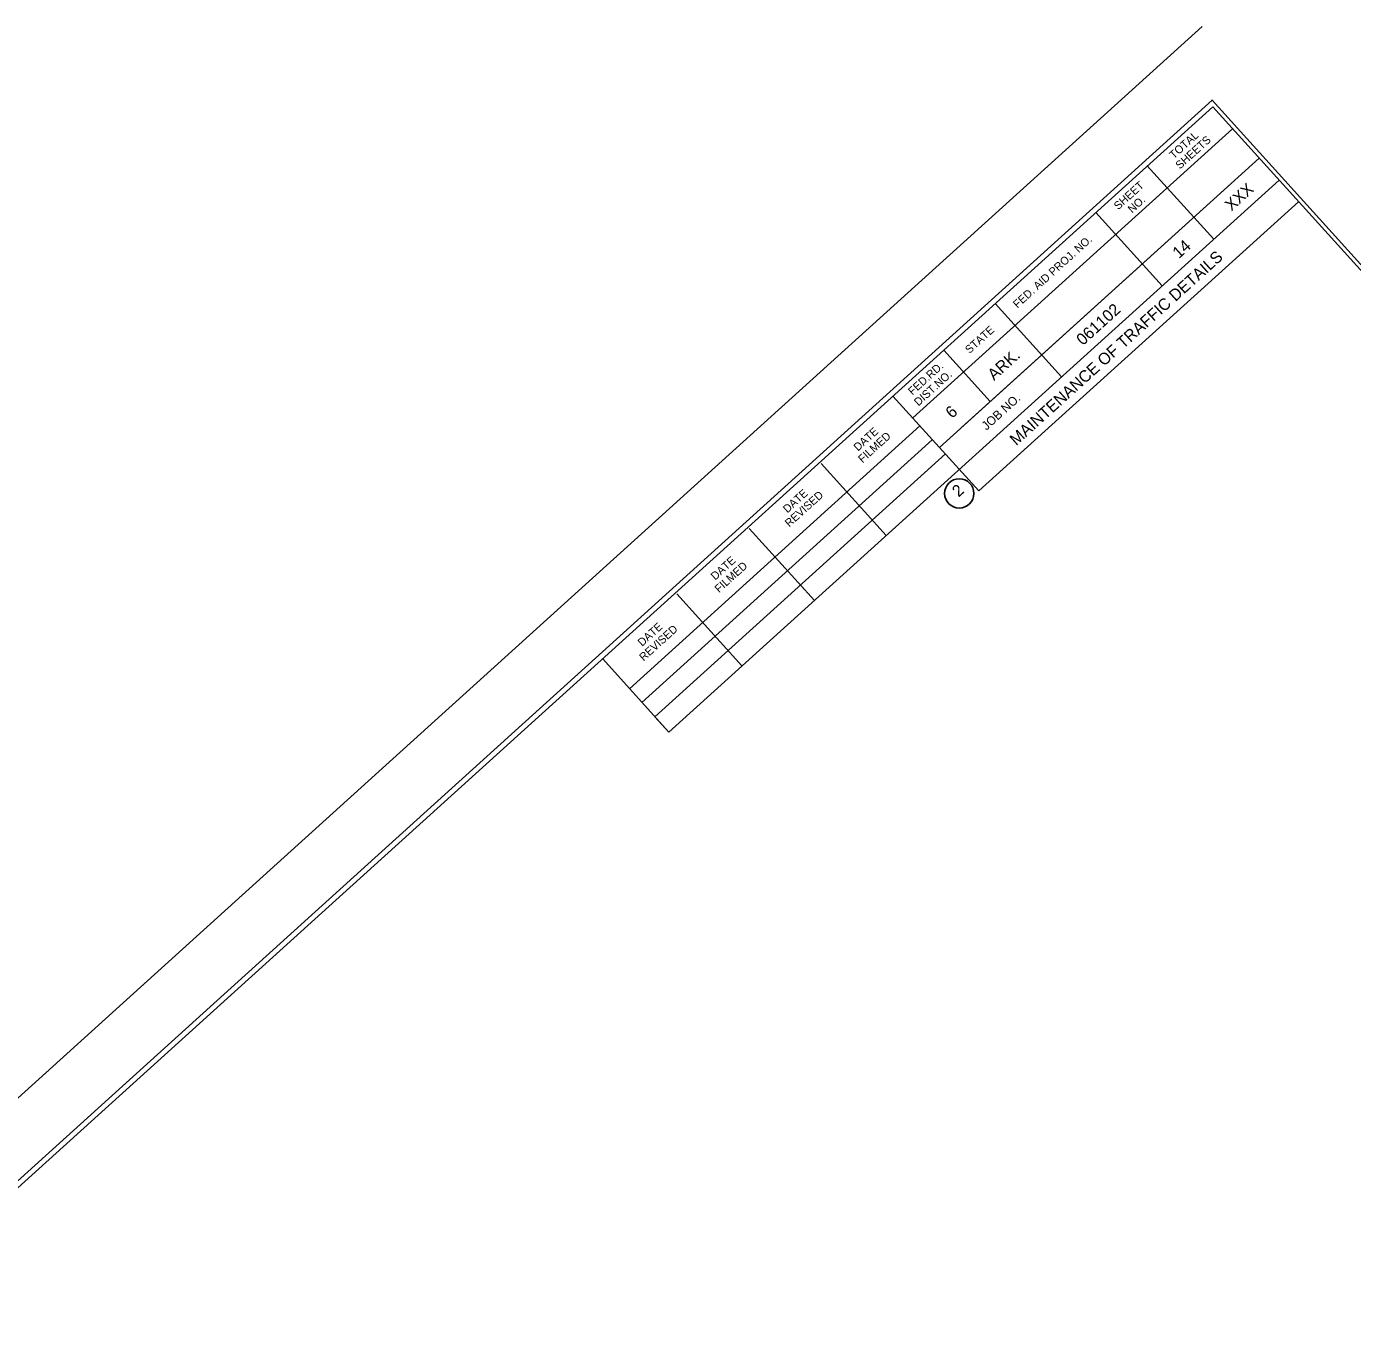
# Model space of a CAD drawing. Extents: x 1307930 to 1312775, y 238372 to 242903.
# Drawn here: x 1311449 to 1312112, y 242257 to 242903 of the extents above; entities that cross this region are included whole.
import ezdxf

# ---------------------------------------------------------------- set-up
doc = ezdxf.new("R2010")
doc.units = 0
doc.layers.add('R_Base', color=7, linetype='Continuous')

msp = doc.modelspace()

# ---------------------------------------------------------------- linework, layer by layer
at = {"layer": 'R_Base'}
for p, q in [((1312036.92, 242903.07), (1310731.77, 241722.32)), ((1310869.87, 241802.41), (1312042.27, 242862.95)), ((1312731.45, 242101.12), (1312042.27, 242862.95)), ((1312052.16, 242851.94), (1311892.32, 242707.47)), ((1312052.07, 242852.12), (1312052.07, 242852.12)), ((1312065.55, 242837.21), (1311905.67, 242692.65)), ((1311916.64, 242702.57), (1312065.55, 242837.21)), ((1312009.54, 242833.47), (1312042.75, 242796.76)), ((1312075.41, 242826.31), (1311770.33, 242550.39)), ((1311925.33, 242670.92), (1312085.17, 242815.52)), ((1311983.8, 242810.12), (1312016.91, 242773.52)), ((1311933.52, 242764.56), (1311966.63, 242727.97)), ((1311907.82, 242741.32), (1311931.03, 242715.59)), ((1311882.32, 242718.31), (1311925.33, 242670.92)), ((1311750.64, 242572.08), (1311895.82, 242703.43)), ((1311756.91, 242565.22), (1311902.08, 242696.54)), ((1311763.39, 242558.06), (1311908.62, 242689.45)), ((1311879.01, 242648.7), (1311846.54, 242684.6)), ((1311843.11, 242616.16), (1311810.57, 242652.13)), ((1311806.85, 242583.43), (1311774.42, 242619.43)), ((1311770.33, 242550.39), (1311737.19, 242587.09)), ((1311770.33, 242550.39), (1311763.39, 242558.06))]:
    msp.add_line(p, q, dxfattribs=at)
msp.add_lwpolyline([(1311559.26, 241037.27), (1312734.62, 242100.55), (1312041.96, 242866.31), (1310866.55, 241802.92)], close=True, dxfattribs=at)
msp.add_circle((1311915.55, 242669.67), 7.33, dxfattribs=at)

# ---------------------------------------------------------------- texts
for s, height, rotation, p in [('TOTAL', 4, 42.1337, (1312022.78, 242836.63)), ('SHEETS', 4, 42.1337, (1312025.85, 242831.51)), ('SHEET', 4, 42.1337, (1311995.01, 242811.17)), ('XXX', 5.85, 42.13376, (1312051.62, 242810.55)), ('NO.', 4, 42.1337, (1312001.97, 242809.58)), ('FED. AID PROJ. NO.', 4, 42.1337, (1311944.63, 242762.02)), ('14', 5.85, 42.13376, (1312025.38, 242786.82)), ('MAINTENANCE OF TRAFFIC DETAILS', 5.85, 42.13376, (1311944.03, 242693.31)), ('061102', 5.85, 42.13376, (1311977.31, 242743.33)), ('STATE', 4, 42.1337, (1311920.66, 242739.33)), ('ARK.', 5.861, 42.1337, (1311932.96, 242725.83)), ('FED.RD.', 4, 42.1337, (1311892.16, 242718.53)), ('DIST.NO.', 4, 42.1337, (1311895.13, 242713.12)), ('JOB NO.', 4.396, 42.1337, (1311929.15, 242700.97)), ('6', 5.86, 42.1337, (1311911.94, 242706.88)), ('DATE', 4, 42.1337, (1311864.91, 242690.57)), ('FILMED', 4, 42.1337, (1311867.19, 242684.68)), ('DATE', 4, 42.1337, (1311829.64, 242659.66)), ('REVISED', 4, 42.1337, (1311830.57, 242652.62)), ('2', 5.86, 42.1337, (1311915.21, 242667.56)), ('DATE', 4, 42.1337, (1311793.54, 242626.08)), ('FILMED', 4, 42.1337, (1311795.48, 242619.81)), ('DATE', 4, 42.1337, (1311757.02, 242592.97)), ('REVISED', 4, 42.1337, (1311757.76, 242585.62))]:
    msp.add_text(s, height=height, rotation=rotation, dxfattribs=at).set_placement(p)

doc.saveas('drawing.dxf')
